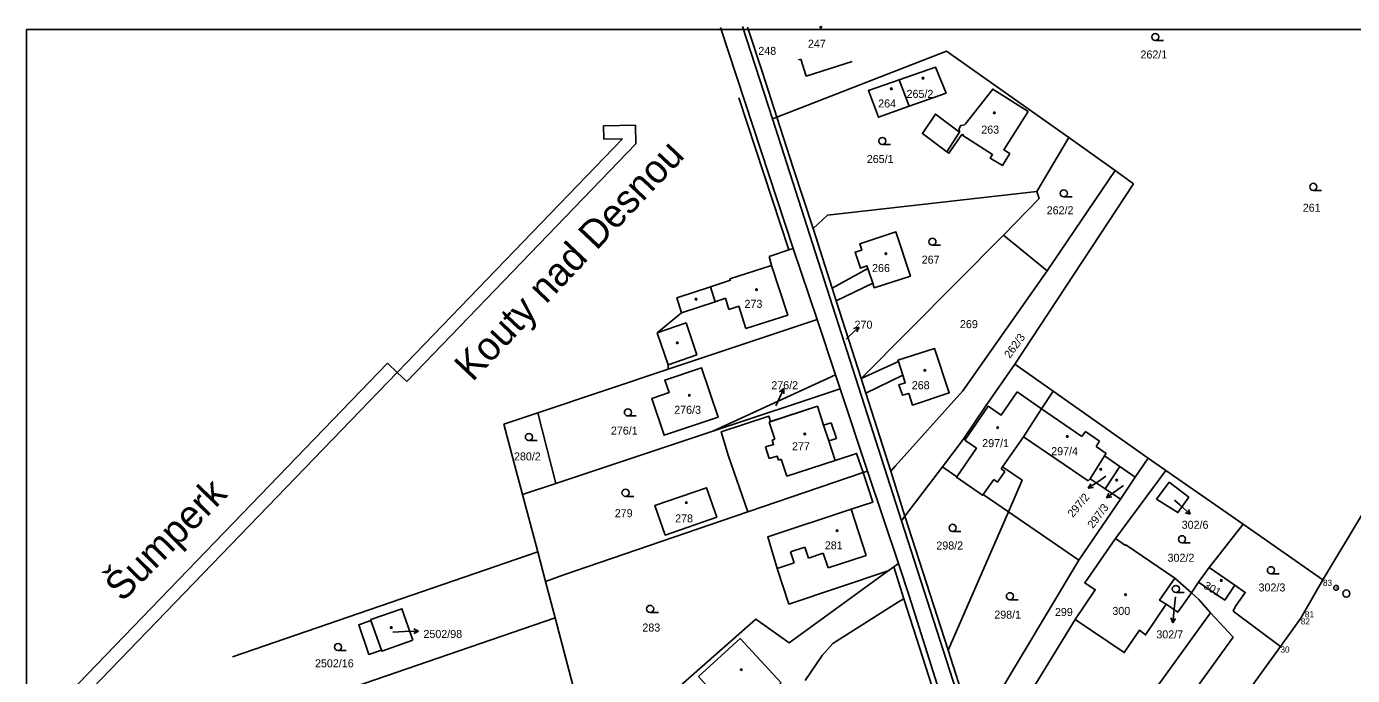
# Model space of a CAD drawing. Extents: x -558358 to -557517, y -1073785 to -1073189.
# Drawn here: x -558357.5 to -558075.9, y -1073327.3 to -1073189.5 of the extents above; entities that cross this region are included whole.
import ezdxf

# ---------------------------------------------------------------- set-up
doc = ezdxf.new("R2010")
doc.units = 0
for name, color, linetype in [('Hranice parcel', 7, 'Continuous'), ('Návěst místo trati', 7, 'Continuous'), ('Parcelní čísla', 7, 'Continuous'), ('Pop  PČ popisy', 7, 'Continuous'), ('Rozpiska_pole_1', 7, 'Continuous'), ('Svazek obcí údolí Desné', 7, 'Continuous'), ('Vnitřní kresba', 7, 'Continuous'), ('Vrstva 60', 7, 'Continuous'), ('Značky budov', 7, 'Continuous'), ('Značky kultur', 7, 'Continuous')]:
    doc.layers.add(name, color=color, linetype=linetype)

msp = doc.modelspace()

# ---------------------------------------------------------------- linework, layer by layer
at = {"layer": 'Hranice parcel'}
for p, q in [((-558199.08, -1073209.06), (-558205.49, -1073189.45)), ((-558201.24, -1073199.21), (-558204.37, -1073189.6)), ((-558198.15, -1073208.7), (-558162.11, -1073194.7)), ((-558162.11, -1073194.7), (-558136.18, -1073212.99)), ((-558198.15, -1073208.7), (-558201.24, -1073199.21)), ((-558170.04, -1073206.37), (-558172.21, -1073200.74)), ((-558195.64, -1073236.88), (-558206.21, -1073204.6)), ((-558199.08, -1073209.06), (-558198.15, -1073208.7)), ((-558171.71, -1073294.39), (-558199.08, -1073209.06)), ((-558136.18, -1073212.99), (-558142.95, -1073224.45)), ((-558136.18, -1073212.99), (-558126.3, -1073220.06)), ((-558140.75, -1073241.36), (-558126.3, -1073220.06)), ((-558126.3, -1073220.06), (-558122.4, -1073222.85)), ((-558122.4, -1073222.85), (-558147.61, -1073261.18)), ((-558190.48, -1073232.36), (-558186.42, -1073245.02)), ((-558180.27, -1073264.19), (-558150.02, -1073233.76)), ((-558150.02, -1073233.76), (-558140.75, -1073241.36)), ((-558194.69, -1073236.56), (-558195.64, -1073236.88)), ((-558194.69, -1073236.56), (-558189.64, -1073251.69)), ((-558199.8, -1073238.31), (-558195.64, -1073236.88)), ((-558186.42, -1073245.02), (-558185.55, -1073247.73)), ((-558185.55, -1073247.73), (-558180.27, -1073264.19)), ((-558221.22, -1073262.24), (-558189.64, -1073251.69)), ((-558189.64, -1073251.69), (-558185.73, -1073263.4)), ((-558147.61, -1073261.18), (-558139.47, -1073266.91)), ((-558248.97, -1073271.5), (-558221.22, -1073262.24)), ((-558211.74, -1073275.38), (-558185.73, -1073263.4)), ((-558185.73, -1073263.4), (-558184.74, -1073266.37)), ((-558180.27, -1073264.19), (-558179.28, -1073267.3)), ((-558184.74, -1073266.37), (-558211.74, -1073275.38)), ((-558184.74, -1073266.37), (-558178.92, -1073283.85)), ((-558179.28, -1073267.3), (-558173.98, -1073283.88)), ((-558139.47, -1073266.91), (-558119.31, -1073281.1)), ((-558256.16, -1073273.9), (-558248.97, -1073271.5)), ((-558248.97, -1073271.5), (-558245.1, -1073286.51)), ((-558254.1, -1073281.66), (-558256.16, -1073273.9)), ((-558211.74, -1073275.38), (-558245.1, -1073286.51)), ((-558185.53, -1073276.94), (-558186.65, -1073273.58)), ((-558122.04, -1073285.13), (-558119.31, -1073281.1)), ((-558119.31, -1073281.1), (-558115.55, -1073283.75)), ((-558252.2, -1073288.86), (-558254.1, -1073281.66)), ((-558204.33, -1073292.51), (-558179.86, -1073284.17)), ((-558179.86, -1073284.17), (-558178.92, -1073283.85)), ((-558178.92, -1073283.85), (-558172.36, -1073303.47)), ((-558173.98, -1073283.88), (-558170.97, -1073293.42)), ((-558170.97, -1073293.42), (-558163.02, -1073282.94)), ((-558128.43, -1073287.66), (-558125.31, -1073282.88)), ((-558126.22, -1073298.15), (-558115.55, -1073283.75)), ((-558122.04, -1073285.13), (-558125.31, -1073282.88)), ((-558115.55, -1073283.75), (-558099.14, -1073295.15)), ((-558245.1, -1073286.51), (-558252.2, -1073288.86)), ((-558125.21, -1073289.82), (-558122.04, -1073285.13)), ((-558252.2, -1073288.86), (-558248.97, -1073301.04)), ((-558134.04, -1073302.76), (-558125.21, -1073289.82)), ((-558128.43, -1073287.66), (-558125.21, -1073289.82)), ((-558149, -1073292.52), (-558161.8, -1073321.91)), ((-558149, -1073292.52), (-558134.04, -1073302.76)), ((-558171.71, -1073294.39), (-558170.97, -1073293.42)), ((-558161.8, -1073321.91), (-558170.97, -1073293.42)), ((-558106.35, -1073304.33), (-558099.14, -1073295.15)), ((-558099.14, -1073295.15), (-558082.18, -1073306.93)), ((-558313.8, -1073323.28), (-558248.97, -1073301.04)), ((-558248.97, -1073301.04), (-558247.31, -1073307.29)), ((-558173.36, -1073304.2), (-558172.36, -1073303.47)), ((-558156.12, -1073339.58), (-558134.04, -1073302.76)), ((-558174.53, -1073305.05), (-558173.36, -1073304.2)), ((-558171.18, -1073310.99), (-558173.36, -1073304.2)), ((-558113.61, -1073306.59), (-558110.09, -1073309.68)), ((-558106.35, -1073304.33), (-558108.61, -1073307.47)), ((-558100.91, -1073308.09), (-558106.35, -1073304.33)), ((-558247.31, -1073307.29), (-558245.27, -1073315.03)), ((-558110.09, -1073309.68), (-558108.61, -1073307.47)), ((-558171.18, -1073310.99), (-558158.75, -1073349.79)), ((-558245.27, -1073315.03), (-558311.02, -1073337.58)), ((-558245.27, -1073315.03), (-558240.15, -1073334.41)), ((-558153.86, -1073346.35), (-558134.81, -1073315.38)), ((-558146.53, -1073369.85), (-558106.1, -1073313.94)), ((-558101.25, -1073313.61), (-558091.21, -1073321.1)), ((-558156.12, -1073339.58), (-558161.8, -1073321.91))]:
    msp.add_line(p, q, dxfattribs=at)
for points in [[(-558194.69, -1073236.56), (-558210.13, -1073189.63)], [(-558172.21, -1073200.74), (-558164.51, -1073198.05), (-558162.21, -1073203.59), (-558170.04, -1073206.37)], [(-558172.21, -1073200.74), (-558178.74, -1073203.06), (-558176.58, -1073208.71), (-558170.04, -1073206.37)], [(-558159.35, -1073211.86), (-558164.49, -1073208.05), (-558167.25, -1073212.17), (-558162.05, -1073216.04), (-558161.61, -1073216.37), (-558158.87, -1073212.35), (-558158.54, -1073212.45), (-558158.65, -1073212.62), (-558152.39, -1073216.66), (-558152.86, -1073217.38), (-558150.28, -1073218.99), (-558148.7, -1073216.44), (-558149.97, -1073215.63), (-558144.81, -1073207.5), (-558152.32, -1073202.74), (-558158.11, -1073210.08), (-558158.35, -1073210.31), (-558159.12, -1073210.49), (-558159.48, -1073211.13), (-558159.35, -1073211.86)], [(-558198.15, -1073208.7), (-558194.7, -1073219.45), (-558190.48, -1073232.36)], [(-558190.48, -1073232.36), (-558187.44, -1073229.54), (-558142.95, -1073224.45)], [(-558142.95, -1073224.45), (-558142.49, -1073225.95), (-558150.02, -1073233.76)], [(-558185.55, -1073247.73), (-558177.82, -1073243.95), (-558177.49, -1073244.94), (-558169.79, -1073242.44), (-558172.9, -1073233.07), (-558180.56, -1073235.6), (-558180.13, -1073236.92), (-558181.54, -1073237.39), (-558180.43, -1073240.78), (-558179.03, -1073240.27), (-558178.83, -1073240.86), (-558186.42, -1073245.02)], [(-558199.8, -1073238.31), (-558199.29, -1073240.2), (-558208.14, -1073243.05), (-558208.05, -1073243.33), (-558212.29, -1073244.72), (-558219.4, -1073247.05), (-558218.39, -1073250.28), (-558223.57, -1073254.53), (-558221.27, -1073261.29), (-558221.22, -1073262.24)], [(-558140.75, -1073241.36), (-558158.68, -1073266.81), (-558173.01, -1073282.83), (-558173.98, -1073283.88)], [(-558179.28, -1073267.3), (-558171.41, -1073263.5), (-558170.89, -1073265.11), (-558172.23, -1073265.52), (-558171.5, -1073267.74), (-558170.17, -1073267.35), (-558169.36, -1073269.84), (-558161.57, -1073267.22), (-558164.69, -1073257.79), (-558172.45, -1073260.31), (-558172.35, -1073260.6), (-558180.27, -1073264.19)], [(-558163.02, -1073282.94), (-558158.61, -1073277.12), (-558153.96, -1073270.21), (-558147.61, -1073261.18)], [(-558210.64, -1073272.4), (-558222.13, -1073276.25), (-558224.75, -1073268.45), (-558221.07, -1073267.2), (-558221.97, -1073264.55), (-558214.15, -1073261.94), (-558210.64, -1073272.4)], [(-558149, -1073292.52), (-558146.08, -1073285.8), (-558150.24, -1073282.94), (-558145.79, -1073276.6), (-558141.97, -1073270.62), (-558139.47, -1073266.91)], [(-558186.65, -1073273.58), (-558188.24, -1073274.09), (-558189.55, -1073270.09), (-558199.49, -1073273.33), (-558199.86, -1073272.19), (-558209.99, -1073275.5), (-558208.43, -1073280.69), (-558204.33, -1073292.51)], [(-558179.86, -1073284.17), (-558181.24, -1073280.09), (-558185.8, -1073281.59), (-558187.15, -1073277.46), (-558185.53, -1073276.94)], [(-558125.31, -1073282.88), (-558128.57, -1073280.64), (-558131.66, -1073285.5), (-558128.43, -1073287.66)], [(-558179.86, -1073284.17), (-558177.8, -1073290.48), (-558182.36, -1073291.97), (-558200.11, -1073297.8), (-558198.12, -1073304.57), (-558195.6, -1073312.09), (-558174.53, -1073305.05)], [(-558163.02, -1073282.94), (-558159.92, -1073285.05), (-558159.98, -1073285.15), (-558154.48, -1073289), (-558154.38, -1073288.84), (-558149, -1073292.52)], [(-558114.88, -1073286.21), (-558110.67, -1073289.41), (-558112.99, -1073292.67), (-558117.52, -1073289.79), (-558114.88, -1073286.21)], [(-558210.92, -1073293.66), (-558221.88, -1073297.46), (-558224.1, -1073291.16), (-558213.08, -1073287.38), (-558210.92, -1073293.66)], [(-558247.31, -1073307.29), (-558243.66, -1073305.93), (-558204.33, -1073292.51)], [(-558140.29, -1073392.34), (-558154.66, -1073347.35), (-558171.71, -1073294.39)], [(-558134.81, -1073315.38), (-558130.55, -1073309.06), (-558132.76, -1073307.6), (-558126.22, -1073298.15)], [(-558113.61, -1073306.59), (-558124.02, -1073299.5), (-558124.12, -1073299.64), (-558126.22, -1073298.15)], [(-558172.36, -1073303.47), (-558170.06, -1073310.34), (-558157.85, -1073349.12), (-558143.83, -1073396.83)], [(-558237.16, -1073345.74), (-558202.67, -1073315.29), (-558195.58, -1073320.33), (-558174.53, -1073305.05)], [(-558115.48, -1073312.12), (-558116.87, -1073311.27), (-558113.61, -1073306.59)], [(-558110.09, -1073309.68), (-558113.01, -1073313.83), (-558115.48, -1073312.12)], [(-558106.1, -1073313.94), (-558108.58, -1073311.13), (-558110.09, -1073309.68)], [(-558108.61, -1073307.47), (-558103.03, -1073311.24), (-558100.91, -1073308.09)], [(-558100.91, -1073308.09), (-558098.7, -1073309.62), (-558100.86, -1073312.72), (-558101.25, -1073313.61)], [(-558192.17, -1073328.33), (-558188.55, -1073322.99), (-558186.3, -1073320.49), (-558172.32, -1073311.63), (-558171.18, -1073310.99)], [(-558134.81, -1073315.38), (-558124.37, -1073322.4), (-558121.16, -1073317.67), (-558119.85, -1073318.64), (-558115.48, -1073312.12)], [(-558275.45, -1073319.73), (-558282.1, -1073322.07), (-558282.17, -1073321.87), (-558284.8, -1073322.78), (-558286.97, -1073316.53), (-558284.37, -1073315.62), (-558284.44, -1073315.41), (-558277.79, -1073313.08), (-558275.45, -1073319.73)], [(-558106.1, -1073313.94), (-558101.27, -1073319.14), (-558143.89, -1073378.07)], [(-558197.27, -1073328.8), (-558205.94, -1073319.43), (-558214.79, -1073327.48), (-558206.42, -1073336.91), (-558197.27, -1073328.8)]]:
    msp.add_lwpolyline(points, dxfattribs=at)
at = {"layer": 'Návěst místo trati'}
msp.add_line((-558079.43, -1073308.65), (-558079.33, -1073308.65), dxfattribs=at)
for centre, radius in [((-558079.38, -1073308.65), 0.5), ((-558077.22, -1073309.86), 0.75)]:
    msp.add_circle(centre, radius, dxfattribs=at)
at = {"layer": 'Pop  PČ popisy'}
for p, q in [((-558182.95, -1073255.34), (-558180.79, -1073253.26)), ((-558180.79, -1073253.26), (-558181.86, -1073253.59)), ((-558180.79, -1073253.26), (-558181.16, -1073254.31)), ((-558183.46, -1073255.83), (-558182.95, -1073255.34)), ((-558197.94, -1073269.07), (-558196.72, -1073266.33)), ((-558196.72, -1073266.33), (-558197.58, -1073267.04)), ((-558196.72, -1073266.33), (-558196.67, -1073267.45)), ((-558198.36, -1073270.02), (-558197.94, -1073269.07)), ((-558129.56, -1073285.83), (-558132.05, -1073287.51)), ((-558132.05, -1073287.51), (-558131.5, -1073286.53)), ((-558128.29, -1073284.96), (-558129.56, -1073285.83)), ((-558124.56, -1073286.91), (-558125.73, -1073287.76)), ((-558132.05, -1073287.51), (-558130.94, -1073287.36)), ((-558125.73, -1073287.76), (-558128.16, -1073289.52)), ((-558128.16, -1073289.52), (-558127.64, -1073288.53)), ((-558128.16, -1073289.52), (-558127.05, -1073289.34)), ((-558113.72, -1073290), (-558112.59, -1073291.03)), ((-558112.59, -1073291.03), (-558110.36, -1073293.04)), ((-558110.36, -1073293.04), (-558111.44, -1073292.74)), ((-558110.36, -1073293.04), (-558110.77, -1073292)), ((-558113.53, -1073310.57), (-558113.79, -1073313.11)), ((-558114.1, -1073316.09), (-558114.5, -1073315.05)), ((-558113.79, -1073313.11), (-558114.1, -1073316.09)), ((-558114.1, -1073316.09), (-558113.5, -1073315.15)), ((-558279.76, -1073318.04), (-558277.28, -1073317.94)), ((-558277.28, -1073317.94), (-558274.28, -1073317.83)), ((-558274.28, -1073317.83), (-558275.3, -1073317.37)), ((-558274.28, -1073317.83), (-558275.26, -1073318.37))]:
    msp.add_line(p, q, dxfattribs=at)
at = {"layer": 'Rozpiska_pole_1'}
for p, q in [((-558357.53, -1073784.09), (-558357.53, -1073190.09)), ((-558357.53, -1073190.09), (-557516.53, -1073190.09)), ((-558228.16, -1073210.39), (-558235.01, -1073210.51)), ((-558235.01, -1073210.51), (-558234.9, -1073213.34)), ((-558228.09, -1073214.39), (-558228.16, -1073210.39)), ((-558230.95, -1073213.27), (-558278.82, -1073262.89)), ((-558234.9, -1073213.34), (-558230.95, -1073213.27)), ((-558276.78, -1073264.86), (-558228.09, -1073214.39)), ((-558280.86, -1073260.92), (-558348.4, -1073330.92)), ((-558278.82, -1073262.89), (-558280.86, -1073260.92)), ((-558345.54, -1073332.05), (-558278.82, -1073262.89)), ((-558278.82, -1073262.89), (-558276.78, -1073264.86))]:
    msp.add_line(p, q, dxfattribs=at)
at = {"layer": 'Svazek obcí údolí Desné'}
for points in [[(-558082.18, -1073306.93), (-558073.77, -1073292.96), (-558066.53, -1073276.76), (-558060.05, -1073257.85), (-558056.4, -1073244.89), (-558045.6, -1073201.5), (-558043.07, -1073189.63)], [(-558082.18, -1073306.93), (-558086.02, -1073313.63), (-558086.89, -1073315.11), (-558091.21, -1073321.1), (-558099.53, -1073332.65), (-558131.71, -1073378.11), (-558132.32, -1073380.12), (-558138.4, -1073389.94), (-558139.67, -1073391.56)], [(-558082.18, -1073306.93), (-558086.02, -1073313.63), (-558086.89, -1073315.11), (-558091.21, -1073321.1)]]:
    msp.add_lwpolyline(points, dxfattribs=at)
at = {"layer": 'Vnitřní kresba'}
for p, q in [((-558193.6, -1073196.55), (-558193.1, -1073196.39)), ((-558193.1, -1073196.39), (-558191.93, -1073199.98)), ((-558191.93, -1073199.98), (-558182.14, -1073196.86)), ((-558162.05, -1073216.04), (-558159.35, -1073211.86)), ((-558199.29, -1073240.2), (-558195.85, -1073250.73)), ((-558178.83, -1073240.86), (-558177.82, -1073243.95)), ((-558212.29, -1073244.72), (-558211.3, -1073247.89)), ((-558211.3, -1073247.89), (-558209.09, -1073247.14)), ((-558209.09, -1073247.14), (-558208.34, -1073249.51)), ((-558218.39, -1073250.28), (-558211.3, -1073247.89)), ((-558208.34, -1073249.51), (-558206.26, -1073248.85)), ((-558206.26, -1073248.85), (-558204.74, -1073253.59)), ((-558223.57, -1073254.53), (-558217.44, -1073252.39)), ((-558217.44, -1073252.39), (-558215.14, -1073259.16)), ((-558204.74, -1073253.59), (-558195.85, -1073250.73)), ((-558221.27, -1073261.29), (-558215.14, -1073259.16)), ((-558172.35, -1073260.6), (-558171.41, -1073263.5)), ((-558147.14, -1073267.06), (-558141.97, -1073270.62)), ((-558189.55, -1073270.09), (-558199.78, -1073273.49)), ((-558141.97, -1073270.62), (-558133.4, -1073276.52)), ((-558199.78, -1073273.49), (-558198.6, -1073277.11)), ((-558188.24, -1073274.09), (-558187.15, -1073277.46)), ((-558133.4, -1073276.52), (-558132.65, -1073275.44)), ((-558132.65, -1073275.44), (-558129.62, -1073277.52)), ((-558200.56, -1073278.74), (-558199.78, -1073281.19)), ((-558198.6, -1073277.11), (-558199.14, -1073277.31)), ((-558145.79, -1073276.6), (-558132.02, -1073285.94)), ((-558130.36, -1073278.61), (-558129.62, -1073277.52)), ((-558130.36, -1073278.61), (-558128.2, -1073280.1)), ((-558197.83, -1073281.52), (-558197.23, -1073281.35)), ((-558197.23, -1073281.35), (-558196.05, -1073284.95)), ((-558196.05, -1073284.95), (-558185.8, -1073281.59)), ((-558128.57, -1073280.64), (-558128.2, -1073280.1)), ((-558151.33, -1073286.18), (-558149.78, -1073283.94)), ((-558150.56, -1073283.39), (-558150.24, -1073282.94)), ((-558150.56, -1073283.39), (-558149.78, -1073283.94)), ((-558154.38, -1073288.84), (-558152.12, -1073285.63)), ((-558152.12, -1073285.63), (-558151.33, -1073286.18)), ((-558132.02, -1073285.94), (-558131.66, -1073285.5)), ((-558182.36, -1073291.97), (-558179.17, -1073301.77)), ((-558195.29, -1073301.04), (-558192.22, -1073300.02)), ((-558195.29, -1073301.04), (-558194.51, -1073303.36)), ((-558192.22, -1073300.02), (-558191.45, -1073302.33)), ((-558191.45, -1073302.33), (-558188.34, -1073301.29)), ((-558188.34, -1073301.29), (-558187.3, -1073304.42)), ((-558198.12, -1073304.57), (-558194.51, -1073303.36)), ((-558187.3, -1073304.42), (-558179.17, -1073301.77)), ((-558284.37, -1073315.62), (-558282.17, -1073321.87))]:
    msp.add_line(p, q, dxfattribs=at)
for points in [[(-558147.14, -1073267.06), (-558150.53, -1073272.01), (-558153.32, -1073270.09), (-558158.27, -1073277.3)], [(-558200.56, -1073278.74), (-558198.86, -1073278.21), (-558199.14, -1073277.31)], [(-558159.92, -1073285.05), (-558155.77, -1073279.02), (-558158.27, -1073277.3)], [(-558197.83, -1073281.52), (-558198.09, -1073280.68), (-558199.78, -1073281.19)]]:
    msp.add_lwpolyline(points, dxfattribs=at)
at = {"layer": 'Vrstva 60'}
for p, q in [((-558082.18, -1073306.93), (-558082.18, -1073306.93)), ((-558086.89, -1073315.11), (-558086.89, -1073315.11)), ((-558086.02, -1073313.63), (-558086.02, -1073313.63)), ((-558091.21, -1073321.1), (-558091.21, -1073321.1))]:
    msp.add_line(p, q, dxfattribs=at)
at = {"layer": 'Značky budov'}
for centre in [(-558188.83, -1073189.63), (-558173.84, -1073202.67), (-558167.13, -1073200.43), (-558151.98, -1073207.78), (-558175.02, -1073237.7), (-558215.35, -1073247.36), (-558202.48, -1073245.34), (-558219.32, -1073256.62), (-558166.74, -1073262.46), (-558216.76, -1073267.78), (-558192.23, -1073275.99), (-558151.26, -1073274.64), (-558136.46, -1073276.5), (-558129.37, -1073283.49), (-558125.99, -1073285.78), (-558217.39, -1073290.55), (-558185.37, -1073296.51), (-558103.76, -1073307.08), (-558124.11, -1073310.11), (-558280.08, -1073317.09), (-558205.73, -1073326.02)]:
    msp.add_circle(centre, 0.175, dxfattribs=at)
at = {"layer": 'Značky kultur'}
for p, q in [((-558117.8, -1073192.42), (-558116.05, -1073192.42)), ((-558175.76, -1073214.51), (-558174.01, -1073214.51)), ((-558084.24, -1073224.25), (-558082.49, -1073224.25)), ((-558137.22, -1073225.64), (-558135.47, -1073225.64)), ((-558165.13, -1073235.9), (-558163.38, -1073235.9)), ((-558229.81, -1073272.15), (-558228.06, -1073272.15)), ((-558250.84, -1073277.37), (-558249.09, -1073277.37)), ((-558230.31, -1073289.22), (-558228.56, -1073289.22)), ((-558160.84, -1073296.66), (-558159.09, -1073296.66)), ((-558112.12, -1073299.08), (-558110.37, -1073299.08)), ((-558093.24, -1073305.66), (-558091.49, -1073305.66)), ((-558113.43, -1073309.64), (-558111.68, -1073309.64)), ((-558148.68, -1073311.18), (-558146.93, -1073311.18)), ((-558225.08, -1073313.87), (-558223.33, -1073313.87)), ((-558291.38, -1073321.96), (-558289.63, -1073321.96))]:
    msp.add_line(p, q, dxfattribs=at)
for centre in [(-558117.8, -1073191.67), (-558175.76, -1073213.76), (-558137.22, -1073224.89), (-558084.24, -1073223.5), (-558165.13, -1073235.15), (-558229.81, -1073271.4), (-558250.84, -1073276.62), (-558230.31, -1073288.47), (-558160.84, -1073295.91), (-558112.12, -1073298.33), (-558093.24, -1073304.91), (-558148.68, -1073310.43), (-558113.43, -1073308.89), (-558225.08, -1073313.12), (-558291.38, -1073321.21)]:
    msp.add_circle(centre, 0.75, dxfattribs=at)

# ---------------------------------------------------------------- texts
at = {"layer": 'Parcelní čísla'}
for s, p in [('248', (-558202.11, -1073195.47)), ('247', (-558191.57, -1073193.95)), ('262/1', (-558120.95, -1073196.24)), ('264', (-558176.65, -1073206.64)), ('265/2', (-558170.62, -1073204.6)), ('263', (-558154.76, -1073212.19)), ('265/1', (-558179.07, -1073218.43)), ('262/2', (-558140.86, -1073229.32)), ('261', (-558086.47, -1073228.79)), ('267', (-558167.41, -1073239.81)), ('266', (-558177.95, -1073241.59)), ('273', (-558205.04, -1073249.19)), ('270', (-558181.67, -1073253.61)), ('269', (-558159.28, -1073253.5)), ('276/2', (-558199.35, -1073266.48)), ('268', (-558169.52, -1073266.47)), ('276/3', (-558219.97, -1073271.69)), ('276/1', (-558233.42, -1073276.11)), ('277', (-558194.96, -1073279.44)), ('297/1', (-558154.55, -1073278.77)), ('297/4', (-558139.9, -1073280.48)), ('280/2', (-558254, -1073281.59)), ('279', (-558232.59, -1073293.65)), ('278', (-558219.77, -1073294.76)), ('302/6', (-558112.19, -1073296.11)), ('281', (-558187.99, -1073300.48)), ('298/2', (-558164.3, -1073300.51)), ('302/2', (-558115.19, -1073303.11)), ('302/3', (-558095.86, -1073309.42)), ('298/1', (-558151.99, -1073315.19)), ('299', (-558139.11, -1073314.63)), ('300', (-558126.91, -1073314.4)), ('2502/98', (-558273.23, -1073319.29)), ('283', (-558226.73, -1073317.93)), ('302/7', (-558117.57, -1073319.39)), ('2502/16', (-558296.26, -1073325.53))]:
    msp.add_text(s, height=1.7, dxfattribs=at).set_placement(p)
for s, rotation, p in [('262/3', 54, (-558148.67, -1073260.04)), ('297/2', 50, (-558135.3, -1073293.83)), ('297/3', 53, (-558131.02, -1073296.16)), ('301', 330, (-558107.72, -1073308.64))]:
    msp.add_text(s, height=1.7, rotation=rotation, dxfattribs=at).set_placement(p)
at = {"layer": 'Rozpiska_pole_1'}
for s, rotation, p in [('Kouty nad Desnou', 46.6457, (-558262.82, -1073265.06)), ('Šumperk', 45.2335, (-558337.2, -1073311.84))]:
    msp.add_text(s, height=6, rotation=rotation, dxfattribs=at).set_placement(p)
at = {"layer": 'Vrstva 60'}
for s, p in [('83', (-558082.18, -1073308.23)), ('82', (-558086.89, -1073316.41)), ('81', (-558086.02, -1073314.93)), ('30', (-558091.21, -1073322.4))]:
    msp.add_text(s, height=1.3, dxfattribs=at).set_placement(p)

doc.saveas('drawing.dxf')
